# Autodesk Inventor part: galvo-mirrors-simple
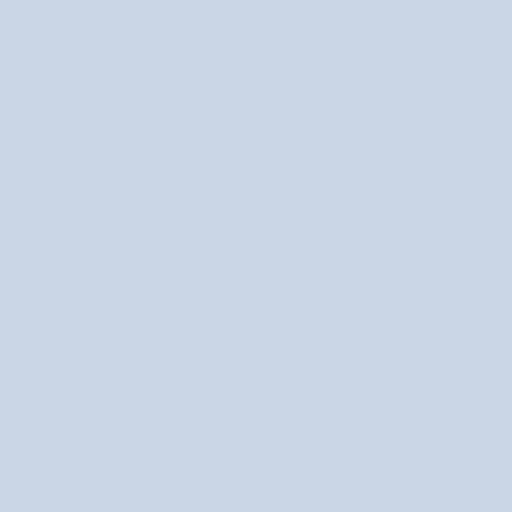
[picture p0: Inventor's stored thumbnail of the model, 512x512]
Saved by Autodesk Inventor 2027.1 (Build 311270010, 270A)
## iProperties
Created: 2026-07
Part Number: galvo-mirrors-simple
Material: Generic
Document SubType Name: Modeling
Designer: dunge
Density: 1 g/cm^3
Appearance: Default
Author: dunge
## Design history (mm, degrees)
